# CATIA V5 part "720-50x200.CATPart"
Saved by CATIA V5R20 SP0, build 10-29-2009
Part number: 720-50x200
Definition: NONE
Nomenclature: 720-50x200
Source: Unknown
Description: 720-50x200
Bounding box of the stored display mesh (mm): x 0 to 200, y -25 to 25, z -25 to 25
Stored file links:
  C:\Users\Utente\Desktop\IO LAVORO\3D X SITO CF\X SITO\720\720-50x200.CATPart

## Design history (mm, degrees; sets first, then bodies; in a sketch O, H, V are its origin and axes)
Body1 "720-50x200" (main body)
  Solid1: solid without history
